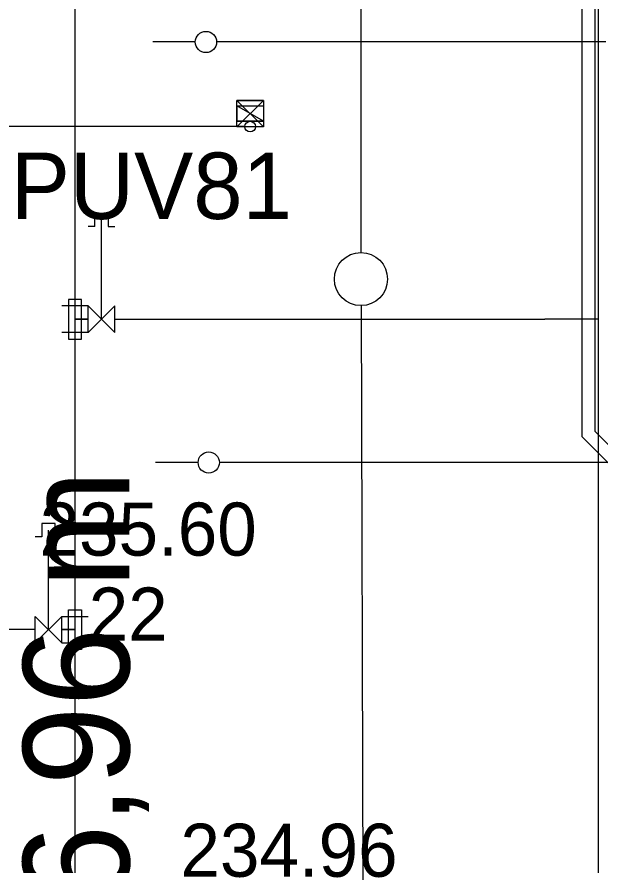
# Model space of a CAD drawing. Extents: x -264234 to -263604, y -1242346 to -1242049.
# Drawn here: x -263925.24 to -263914.26, y -1242207.77 to -1242191.79 of the extents above; entities that cross this region are included whole.
import ezdxf

# ---------------------------------------------------------------- set-up
doc = ezdxf.new("R2010")
doc.units = 0
for name, color, linetype in [('KFA_BODY_CISLO', 7, 'Continuous'), ('KFA_BODY_VYSKA', 7, 'Continuous'), ('KFA_DAZDOVA_KANALIZACIA_vetva_G_popis', 7, 'Continuous'), ('KFA_JESTV_IS_DSP_-_KANAL_DAZD', 7, 'Continuous'), ('KFA_SITUACIA_DSP', 7, 'Continuous'), ('KFA_SO_40-2-II_DK_PRIPOJKY_UV_PROJEKT', 7, 'Continuous'), ('KFA_SO_40-2-II_DK_PRIPOJKY_UV_PROJEKT_popis', 7, 'Continuous'), ('KFA_SO_40-2-II_DK_UV_PROJEKT', 7, 'Continuous')]:
    doc.layers.add(name, color=color, linetype=linetype)

msp = doc.modelspace()

# ---------------------------------------------------------------- linework, layer by layer
at = {"layer": 'KFA_JESTV_IS_DSP_-_KANAL_DAZD'}
for p, q in [((-263918.764, -1242152.564), (-263918.757, -1242196.225)), ((-263918.755, -1242197.225), (-263918.632, -1242236.449))]:
    msp.add_line(p, q, dxfattribs=at)
msp.add_circle((-263918.757, -1242196.725), 0.5, dxfattribs=at)
at = {"layer": 'KFA_SITUACIA_DSP'}
for p, q in [((-263924.143, -1242185.14), (-263924.143, -1242250.14)), ((-263921.877, -1242192.257), (-263922.677, -1242192.257)), ((-263915.293, -1242192.257), (-263921.477, -1242192.257)), ((-263914.143, -1242192.257), (-263915.293, -1242192.257)), ((-263921.093, -1242193.752), (-263921.093, -1242193.462)), ((-263921.093, -1242193.462), (-263920.593, -1242193.462)), ((-263920.593, -1242193.752), (-263921.093, -1242193.462)), ((-263920.593, -1242193.752), (-263921.093, -1242193.462)), ((-263921.093, -1242193.462), (-263921.093, -1242193.752)), ((-263920.593, -1242193.462), (-263920.593, -1242193.752)), ((-263920.593, -1242193.752), (-263921.093, -1242193.752)), ((-263921.093, -1242193.752), (-263920.593, -1242193.752)), ((-263920.944, -1242193.852), (-263925.798, -1242193.852)), ((-263923.768, -1242195.732), (-263923.768, -1242195.482)), ((-263923.768, -1242195.482), (-263923.518, -1242195.482)), ((-263923.518, -1242195.482), (-263923.518, -1242195.732)), ((-263923.643, -1242197.482), (-263923.643, -1242195.607)), ((-263923.768, -1242195.732), (-263923.893, -1242195.732)), ((-263923.518, -1242195.732), (-263923.393, -1242195.732)), ((-263924.018, -1242197.107), (-263924.268, -1242197.107)), ((-263924.268, -1242197.107), (-263924.268, -1242197.857)), ((-263924.018, -1242197.857), (-263924.018, -1242197.107)), ((-263923.893, -1242197.232), (-263924.393, -1242197.232)), ((-263923.893, -1242197.732), (-263923.893, -1242197.232)), ((-263923.893, -1242197.232), (-263923.393, -1242197.732)), ((-263923.393, -1242197.232), (-263923.893, -1242197.732)), ((-263923.393, -1242197.732), (-263923.393, -1242197.232)), ((-263924.143, -1242197.482), (-263923.893, -1242197.482)), ((-263923.893, -1242197.482), (-263924.143, -1242197.482)), ((-263923.393, -1242197.482), (-263915.293, -1242197.482)), ((-263914.293, -1242197.482), (-263915.293, -1242197.482)), ((-263923.893, -1242197.732), (-263924.393, -1242197.732)), ((-263924.268, -1242197.857), (-263924.018, -1242197.857)), ((-263921.824, -1242200.182), (-263922.624, -1242200.182)), ((-263915.293, -1242200.182), (-263921.424, -1242200.182)), ((-263909.043, -1242200.182), (-263915.293, -1242200.182)), ((-263924.768, -1242201.332), (-263924.768, -1242201.582)), ((-263924.518, -1242201.332), (-263924.768, -1242201.332)), ((-263924.518, -1242201.582), (-263924.518, -1242201.332)), ((-263924.768, -1242201.582), (-263924.893, -1242201.582)), ((-263924.643, -1242203.332), (-263924.643, -1242201.457)), ((-263924.518, -1242201.582), (-263924.393, -1242201.582)), ((-263924.268, -1242203.707), (-263924.268, -1242202.957)), ((-263924.268, -1242202.957), (-263924.018, -1242202.957)), ((-263924.018, -1242202.957), (-263924.018, -1242203.707)), ((-263924.893, -1242203.582), (-263924.893, -1242203.082)), ((-263924.393, -1242203.082), (-263924.893, -1242203.582)), ((-263924.893, -1242203.082), (-263924.393, -1242203.582)), ((-263924.393, -1242203.582), (-263924.393, -1242203.082)), ((-263924.393, -1242203.082), (-263923.893, -1242203.082)), ((-263924.893, -1242203.332), (-263958.097, -1242203.332)), ((-263924.143, -1242203.332), (-263924.393, -1242203.332)), ((-263924.393, -1242203.332), (-263924.143, -1242203.332)), ((-263924.393, -1242203.582), (-263923.893, -1242203.582)), ((-263924.018, -1242203.707), (-263924.268, -1242203.707))]:
    msp.add_line(p, q, dxfattribs=at)
msp.add_lwpolyline([(-263893.618, -1242118.282), (-263916.093, -1242118.282), (-263916.093, -1242175.482), (-263914.293, -1242175.482), (-263914.293, -1242210.482), (-263893.618, -1242210.482), (-263893.618, -1242166.382), (-263900.043, -1242166.382), (-263900.043, -1242162.382), (-263893.618, -1242162.382)], close=True, dxfattribs=at)
for points in [[(-263918.593, -1242164.382), (-263914.35, -1242168.625), (-263914.35, -1242199.59), (-263910.108, -1242203.832), (-263891.768, -1242203.832)], [(-263918.696, -1242164.632), (-263914.6, -1242168.728), (-263914.6, -1242199.693), (-263910.211, -1242204.082), (-263891.768, -1242204.082)]]:
    msp.add_lwpolyline(points, dxfattribs=at)
for centre, radius in [((-263921.677, -1242192.257), 0.2), ((-263920.844, -1242193.852), 0.1), ((-263921.624, -1242200.182), 0.2)]:
    msp.add_circle(centre, radius, dxfattribs=at)
at = {"layer": 'KFA_SO_40-2-II_DK_PRIPOJKY_UV_PROJEKT'}
msp.add_lwpolyline([(-263920.944, -1242193.852), (-263925.798, -1242193.852), (-263926.593, -1242194.648)], dxfattribs=at)
at = {"layer": 'KFA_SO_40-2-II_DK_UV_PROJEKT'}
msp.add_lwpolyline([(-263921.093, -1242193.857), (-263921.093, -1242193.357), (-263920.593, -1242193.357), (-263920.593, -1242193.857), (-263921.093, -1242193.857), (-263920.593, -1242193.357), (-263921.093, -1242193.357), (-263920.593, -1242193.857)], dxfattribs=at)

# ---------------------------------------------------------------- texts
at = {"layer": 'KFA_BODY_CISLO'}
msp.add_text('22', height=1, dxfattribs=at).set_placement((-263923.884, -1242203.538))
at = {"layer": 'KFA_BODY_VYSKA'}
for s, p in [('235.60', (-263924.81, -1242201.937)), ('234.96', (-263922.157, -1242207.989))]:
    msp.add_text(s, height=1, dxfattribs=at).set_placement(p)
at = {"layer": 'KFA_DAZDOVA_KANALIZACIA_vetva_G_popis'}
msp.add_text('G1, PVC DN300 - 16,96 m', height=2, rotation=90, dxfattribs=at).set_placement((-263923.121, -1242231.981))
at = {"layer": 'KFA_SO_40-2-II_DK_PRIPOJKY_UV_PROJEKT_popis'}
msp.add_text('PUV81', height=1.25, dxfattribs=at).set_placement((-263925.353, -1242195.592))

doc.saveas('drawing.dxf')
